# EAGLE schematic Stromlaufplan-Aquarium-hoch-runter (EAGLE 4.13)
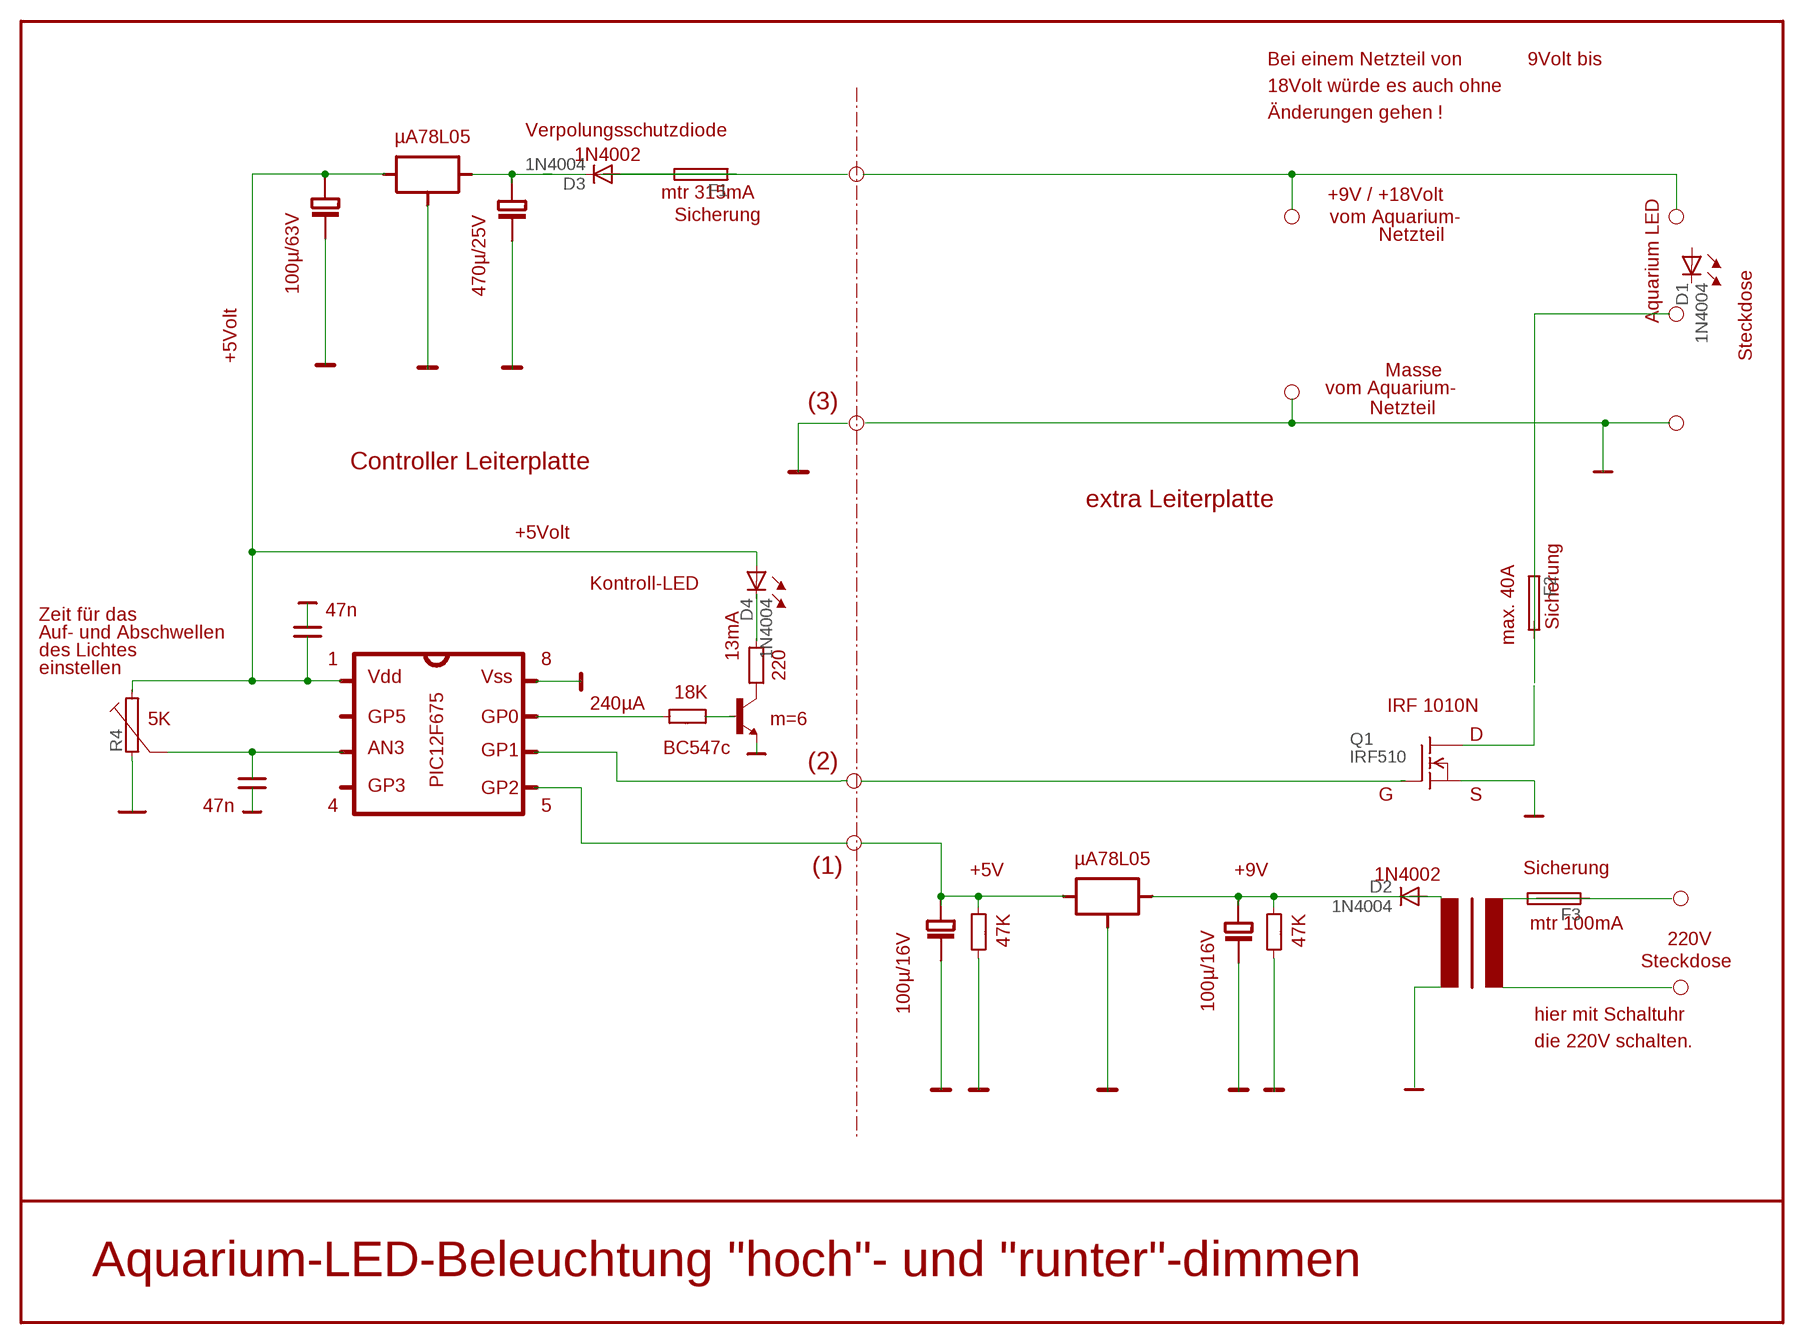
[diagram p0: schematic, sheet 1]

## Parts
D1  1N4004  [DO41-10]
D2  1N4004  [DO41-10]
D3  1N4004  [DO41-10]
D4  1N4004  [DO41-10]
F1  19559  [19559]
F2  19559  [19559]
F3  19559  [19559]
Q1  IRF510  [TO220]
R4  RHS10  [HS10]

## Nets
N$1: D4.A R4.2
N$8: Q1.2(D)
N$13: Q1.3(S)
N$19: F2.1
N$22: D4.C
N$24: F2.2
N$25: F3.1 F3.2
N$30: D2.C
N$31: D2.A
N$33: Q1.1(G)
N$35: D3.C
N$47: D3.A F1.1 F1.2
N$72: R4.1
Unconnected: D1.A D1.C

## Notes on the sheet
- Bei einem Netzteil von | 9Volt bis
- 18Volt würde es auch ohne
- Änderungen gehen !
- Verpolungsschutzdiode
- µA78L05
- 1N4002
- mtr 315mA | +9V / +18Volt | Aquarium LED
- Sicherung
- vom Aquarium-
- Netzteil
- 100µ/63V | 470µ/25V
- +5Volt | Steckdose
- Masse
- vom Aquarium-
- (3) | Netzteil
- Controller Leiterplatte
- extra Leiterplatte
- +5Volt
- Sicherung
- Kontroll-LED
- Zeit für das | 47n
- Auf- und Abschwellen
- max. 40A
- des Lichtes | 13mA
- 1 | 8
- einstellen
- Vdd | Vss | 220
- 18K
- 240µA | IRF 1010N
- 5K | GP5 | GP0 | m=6
- D
- AN3 | GP1 | BC547c
- (2)
- GP3 | PIC12F675
- 47n | GP2
- G | S
- 4 | 5
- µA78L05 | Sicherung
- (1) | +5V | +9V
- 1N4002
- mtr 100mA
- 47K | 47K | 220V
- Steckdose
- 100µ/16V | 100µ/16V
- hier mit Schaltuhr
- die 220V schalten.
- Aquarium-LED-Beleuchtung "hoch"- und "runter"-dimmen

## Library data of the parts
D1-D4 = diode:1N4004: DIODE
F1-F3 = fuse:19559: FUSE HOLDER
Q1 = transistor-fet:IRF510: N-Channel Enhancement MOSFET (HEXFET); 100V; 5,6A; 0,54Ohm
R4 = resistor-power:R: Power Resitor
